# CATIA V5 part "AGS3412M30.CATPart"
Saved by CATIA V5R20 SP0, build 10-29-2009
Part number: AGS3412M30
Definition: NONE
Nomenclature: AGS3412M30
Source: Unknown
Description: AGS3412M30
Bounding box of the stored display mesh (mm): x -33 to 35, y -32.5 to 32.5, z -32.5 to 32.5
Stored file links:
  C:\Users\Utente\Desktop\IO LAVORO\3D X SITO CF\X SITO\PLASTICA\AGS\AGS3412M30.CATPart
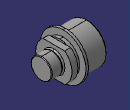
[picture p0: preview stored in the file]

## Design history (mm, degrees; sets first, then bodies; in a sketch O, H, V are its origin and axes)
Body1 "AGS3412M30" (main body)
  Solid1: solid without history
